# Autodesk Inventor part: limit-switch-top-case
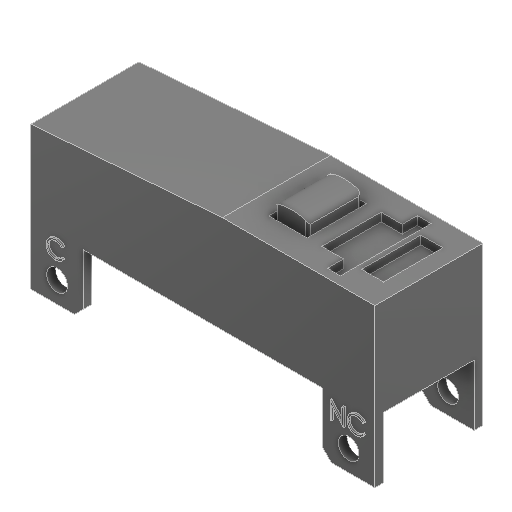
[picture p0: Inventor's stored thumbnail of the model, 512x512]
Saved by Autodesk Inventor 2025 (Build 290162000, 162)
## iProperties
Created: 2025-10
Part Number: limit-switch-top-case
Material: Generico
Document SubType Name: Modeling
Designer: Ryzen5700u
Density: 1 g/cm^3
Appearance: Default
Author: Ryzen5700u
Revision Number: ANY
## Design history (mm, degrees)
feature "Boss-Extrude3"
node "Solido1"
